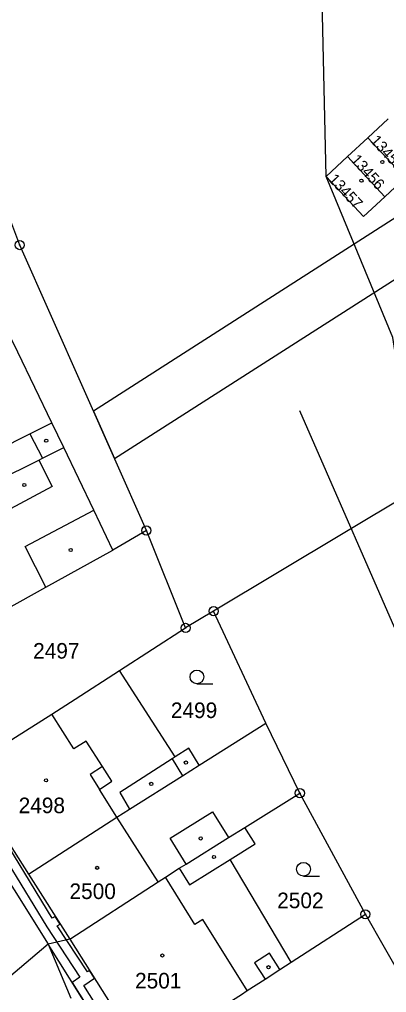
# Model space of a CAD drawing. Extents: x -821458 to -820266, y -1071458 to -1069826.
# Drawn here: x -820683.2 to -820643.1, y -1071211.7 to -1071105.6 of the extents above; entities that cross this region are included whole.
import ezdxf

# ---------------------------------------------------------------- set-up
doc = ezdxf.new("R2010")
doc.units = 0
for name, color, linetype in [('Vrstva 1', 7, 'Continuous'), ('Vrstva 13', 7, 'Continuous'), ('Vrstva 2', 7, 'Continuous'), ('Vrstva 3', 7, 'Continuous'), ('Vrstva 4', 7, 'Continuous'), ('Vrstva 5', 7, 'Continuous'), ('Vrstva 6', 7, 'Continuous'), ('Vrstva 8', 7, 'Continuous')]:
    doc.layers.add(name, color=color, linetype=linetype)

msp = doc.modelspace()

# ---------------------------------------------------------------- linework, layer by layer
at = {"layer": 'Vrstva 1'}
for p, q in [((-820642.94, -1071116.4), (-820645.16, -1071118.45)), ((-820645.16, -1071118.45), (-820647.4, -1071120.52)), ((-820645.16, -1071118.45), (-820641.09, -1071122.84)), ((-820647.4, -1071120.52), (-820643.33, -1071124.91)), ((-820643.33, -1071124.91), (-820641.09, -1071122.84)), ((-820637.33, -1071155.3), (-820662, -1071170.07)), ((-820669.33, -1071161.28), (-820672.99, -1071163.41)), ((-820665.05, -1071171.9), (-820669.33, -1071161.28)), ((-820662, -1071170.07), (-820665.05, -1071171.9)), ((-820656.29, -1071182.27), (-820662, -1071170.07)), ((-820672.26, -1071176.55), (-820665.05, -1071171.9)), ((-820663.57, -1071186.87), (-820656.29, -1071182.27)), ((-820652.59, -1071189.92), (-820656.29, -1071182.27)), ((-820689.38, -1071187.46), (-820682.2, -1071198.75)), ((-820658.59, -1071193.65), (-820652.59, -1071189.92)), ((-820645.44, -1071203.12), (-820652.59, -1071189.92)), ((-820682.2, -1071198.75), (-820677.69, -1071205.82)), ((-820653.54, -1071208.36), (-820645.44, -1071203.12)), ((-820680.04, -1071206.39), (-820688.08, -1071213.18)), ((-820677.69, -1071205.82), (-820680.04, -1071206.39)), ((-820677.69, -1071205.82), (-820669.63, -1071218.58))]:
    msp.add_line(p, q, dxfattribs=at)
for points in [[(-820669.33, -1071161.28), (-820683.15, -1071130.16), (-820686.65, -1071120.86), (-820710.89, -1071054.09), (-820724.52, -1071012.19), (-820736.51, -1070978.31)], [(-820761.23, -1071044.95), (-820734.74, -1071105.53), (-820721.97, -1071129.66), (-820703.01, -1071165.5), (-820691.2, -1071188.61), (-820680.04, -1071206.39)], [(-820637.33, -1071155.3), (-820640.67, -1071151.76), (-820642.44, -1071140.23), (-820649.73, -1071122.67), (-820650.36, -1071093.83)], [(-820647.4, -1071120.52), (-820649.73, -1071122.67), (-820645.63, -1071127.03), (-820643.33, -1071124.91)], [(-820678.34, -1071152.24), (-820679.65, -1071149.54), (-820683.36, -1071141.85), (-820684.26, -1071140)], [(-820701.58, -1071163.92), (-820690.77, -1071158.42), (-820688.61, -1071157.34), (-820685.72, -1071155.91), (-820681.07, -1071153.6), (-820680.65, -1071153.39), (-820678.34, -1071152.24)], [(-820672.99, -1071163.41), (-820675.07, -1071159.07), (-820678.34, -1071152.24)], [(-820695.43, -1071175.71), (-820684.65, -1071169.9), (-820680.32, -1071167.47), (-820672.99, -1071163.41)], [(-820689.38, -1071187.46), (-820679.64, -1071181.29), (-820677.09, -1071179.67), (-820672.26, -1071176.55)], [(-820663.57, -1071186.87), (-820664.7, -1071185.02), (-820666.18, -1071185.96), (-820672.26, -1071176.55)], [(-820682.2, -1071198.75), (-820672.54, -1071192.52), (-820671.16, -1071191.65), (-820665.39, -1071188.01), (-820663.57, -1071186.87)], [(-820677.69, -1071205.82), (-820668.05, -1071199.57), (-820667.26, -1071199.06), (-820665.74, -1071198.11), (-820665, -1071197.65), (-820660.36, -1071194.76), (-820658.59, -1071193.65)], [(-820653.54, -1071208.36), (-820660.2, -1071197.14), (-820657.47, -1071195.44), (-820658.59, -1071193.65)], [(-820637.88, -1071216.32), (-820639.21, -1071214.01), (-820645.44, -1071203.12)], [(-820669.63, -1071218.58), (-820658.95, -1071211.86), (-820658.33, -1071211.45), (-820656.38, -1071210.19), (-820654.76, -1071209.14), (-820653.54, -1071208.36)]]:
    msp.add_lwpolyline(points, dxfattribs=at)
at = {"layer": 'Vrstva 13'}
for points in [[(-820786.23, -1071016.26), (-820788.55, -1071012.81), (-820788.29, -1071014.99), (-820787.07, -1071016.8), (-820778.99, -1071029.73), (-820775.42, -1071035.45), (-820766.12, -1071050.28), (-820760.23, -1071047.52), (-820756.43, -1071055.93), (-820750.24, -1071069.65), (-820743.37, -1071084.86), (-820734.39, -1071104.82), (-820715.9, -1071140.51), (-820706.2, -1071159.17), (-820691.74, -1071187.18), (-820690.76, -1071187.86), (-820687.33, -1071192.87), (-820680.2, -1071204.48), (-820676.58, -1071209.98), (-820677.42, -1071210.57), (-820671.47, -1071220.04)], [(-820669.23, -1071221.87), (-820676.14, -1071210.9), (-820674.99, -1071210.09), (-820675.53, -1071209.25), (-820675.76, -1071209.41), (-820679.07, -1071204.38), (-820678.73, -1071204.19), (-820679.27, -1071203.35), (-820679.61, -1071203.54), (-820686.24, -1071192.73)]]:
    msp.add_lwpolyline(points, dxfattribs=at)
msp.add_lwpolyline([(-820675.1, -1071148.28), (-820672.81, -1071153.44), (-820638.57, -1071131.55), (-820610.44, -1071104.1), (-820600.08, -1071094.97), (-820582.77, -1071081.03), (-820585.78, -1071076.26), (-820603.68, -1071090.69), (-820614.26, -1071100), (-820642.01, -1071127.07)], close=True, dxfattribs=at)
at = {"layer": 'Vrstva 3'}
for p, q in [((-820663.82, -1071178), (-820662.07, -1071178)), ((-820652.19, -1071198.96), (-820650.44, -1071198.96))]:
    msp.add_line(p, q, dxfattribs=at)
for centre in [(-820663.82, -1071177.25), (-820652.19, -1071198.21)]:
    msp.add_circle(centre, 0.75, dxfattribs=at)
at = {"layer": 'Vrstva 4'}
for p, q in [((-820682.06, -1071150.75), (-820679.65, -1071149.54)), ((-820689.87, -1071154.68), (-820682.06, -1071150.75)), ((-820682.06, -1071150.75), (-820680.65, -1071153.39)), ((-820681.07, -1071153.6), (-820679.6, -1071156.49)), ((-820679.6, -1071156.49), (-820684.17, -1071158.9)), ((-820682.54, -1071163.02), (-820675.07, -1071159.07)), ((-820680.32, -1071167.47), (-820682.54, -1071163.02)), ((-820677.24, -1071185.08), (-820679.64, -1071181.29)), ((-820675.91, -1071184.23), (-820677.24, -1071185.08)), ((-820674.13, -1071187.01), (-820675.91, -1071184.23)), ((-820666.51, -1071186.18), (-820672.22, -1071189.84)), ((-820666.18, -1071185.96), (-820666.51, -1071186.18)), ((-820666.51, -1071186.18), (-820665.39, -1071188.01)), ((-820674.13, -1071187.01), (-820675.47, -1071187.9)), ((-820673.11, -1071188.62), (-820674.13, -1071187.01)), ((-820675.47, -1071187.9), (-820674.44, -1071189.52)), ((-820674.44, -1071189.52), (-820673.11, -1071188.62)), ((-820672.54, -1071192.52), (-820674.44, -1071189.52)), ((-820672.22, -1071189.84), (-820671.16, -1071191.65)), ((-820668.05, -1071199.57), (-820672.54, -1071192.52)), ((-820666.75, -1071194.84), (-820662.11, -1071191.95)), ((-820662.11, -1071191.95), (-820660.36, -1071194.76)), ((-820665, -1071197.65), (-820666.75, -1071194.84)), ((-820665.74, -1071198.11), (-820664.63, -1071199.9)), ((-820664.63, -1071199.9), (-820660.2, -1071197.14)), ((-820664.03, -1071204.23), (-820667.26, -1071199.06)), ((-820663.18, -1071203.7), (-820664.03, -1071204.23)), ((-820658.33, -1071211.45), (-820663.18, -1071203.7)), ((-820680.04, -1071206.39), (-820677.58, -1071212.27)), ((-820671.47, -1071220.04), (-820680.04, -1071206.39)), ((-820655.91, -1071207.36), (-820657.53, -1071208.41)), ((-820654.76, -1071209.14), (-820655.91, -1071207.36)), ((-820657.53, -1071208.41), (-820656.38, -1071210.19))]:
    msp.add_line(p, q, dxfattribs=at)
at = {"layer": 'Vrstva 5'}
for centre in [(-820643.59, -1071121.1), (-820645.87, -1071123.14), (-820680.26, -1071151.49), (-820682.65, -1071156.32), (-820677.59, -1071163.4), (-820665.02, -1071186.58), (-820680.28, -1071188.52), (-820668.8, -1071188.91), (-820663.41, -1071194.85), (-820661.96, -1071196.88), (-820674.7, -1071198.06), (-820667.59, -1071207.62), (-820656.01, -1071208.9)]:
    msp.add_circle(centre, 0.175, dxfattribs=at)
at = {"layer": 'Vrstva 6'}
msp.add_line((-820639.69, -1071177.76), (-820652.58, -1071148.22), dxfattribs=at)
at = {"layer": 'Vrstva 8'}
for centre, radius in [((-820683.15, -1071130.16), 0.5), ((-820683.15, -1071130.16), 0.0303), ((-820669.33, -1071161.28), 0.5), ((-820669.33, -1071161.28), 0.0303), ((-820662, -1071170.07), 0.5), ((-820662, -1071170.07), 0.0303), ((-820665.05, -1071171.9), 0.5), ((-820665.05, -1071171.9), 0.0303), ((-820652.59, -1071189.92), 0.5), ((-820652.59, -1071189.92), 0.0303), ((-820645.44, -1071203.12), 0.5), ((-820645.44, -1071203.12), 0.0303)]:
    msp.add_circle(centre, radius, dxfattribs=at)

# ---------------------------------------------------------------- texts
at = {"layer": 'Vrstva 2'}
for s, height, rotation, p in [('13411/21', 1.139, 308, (-820643.96, -1071102.73)), ('13455', 1.2, 312, (-820644.97, -1071118.82)), ('13456', 1.2, 312, (-820647.1, -1071120.92)), ('13457', 1.2, 313, (-820649.54, -1071123.06))]:
    msp.add_text(s, height=height, rotation=rotation, dxfattribs=at).set_placement(p)
for s, p in [('2497', (-820681.69, -1071175.25)), ('2499', (-820666.66, -1071181.73)), ('2498', (-820683.27, -1071192.1)), ('2500', (-820677.72, -1071201.46)), ('2502', (-820655.06, -1071202.46)), ('2501', (-820670.57, -1071211.21))]:
    msp.add_text(s, height=1.7, dxfattribs=at).set_placement(p)

doc.saveas('drawing.dxf')
